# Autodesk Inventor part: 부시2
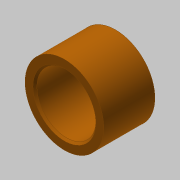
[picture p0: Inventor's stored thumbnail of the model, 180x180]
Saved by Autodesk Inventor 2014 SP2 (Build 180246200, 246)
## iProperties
Created: 2016-08
Part Number: 부시2
Material: 강철, 탄소
Document SubType Name: Modeling
Designer: mduedu
Density: 7.87 g/cm^3
Appearance: 주황색
Author: mduedu
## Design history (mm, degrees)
sketch "스케치1"
  geometry: C1 r 7.5 at (0, 0); C2 r 10 at (0, 0); 1 further point
  constraints: 2 centre point, 2 coincident
  dimensions: "d0" = 15 diameter of C1; "d1" = 20 diameter of C2
extrude "돌출1" new body sketch "스케치1" stored distance "d2" = 13; taper "d3" = 0 deg
chamfer "모따기1" distance "d4" = 0.5; stored, may be unused: second distance "d5" = 2, angle "d6" = 45 deg
node "솔리드1"
